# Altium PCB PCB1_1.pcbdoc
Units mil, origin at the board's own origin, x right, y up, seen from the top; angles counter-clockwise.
Board outline 1868.98 x 1415 mil, 2 copper layers (Top Layer, Bottom Layer); 8 components, 14 nets, 46 pads, 14 vias.
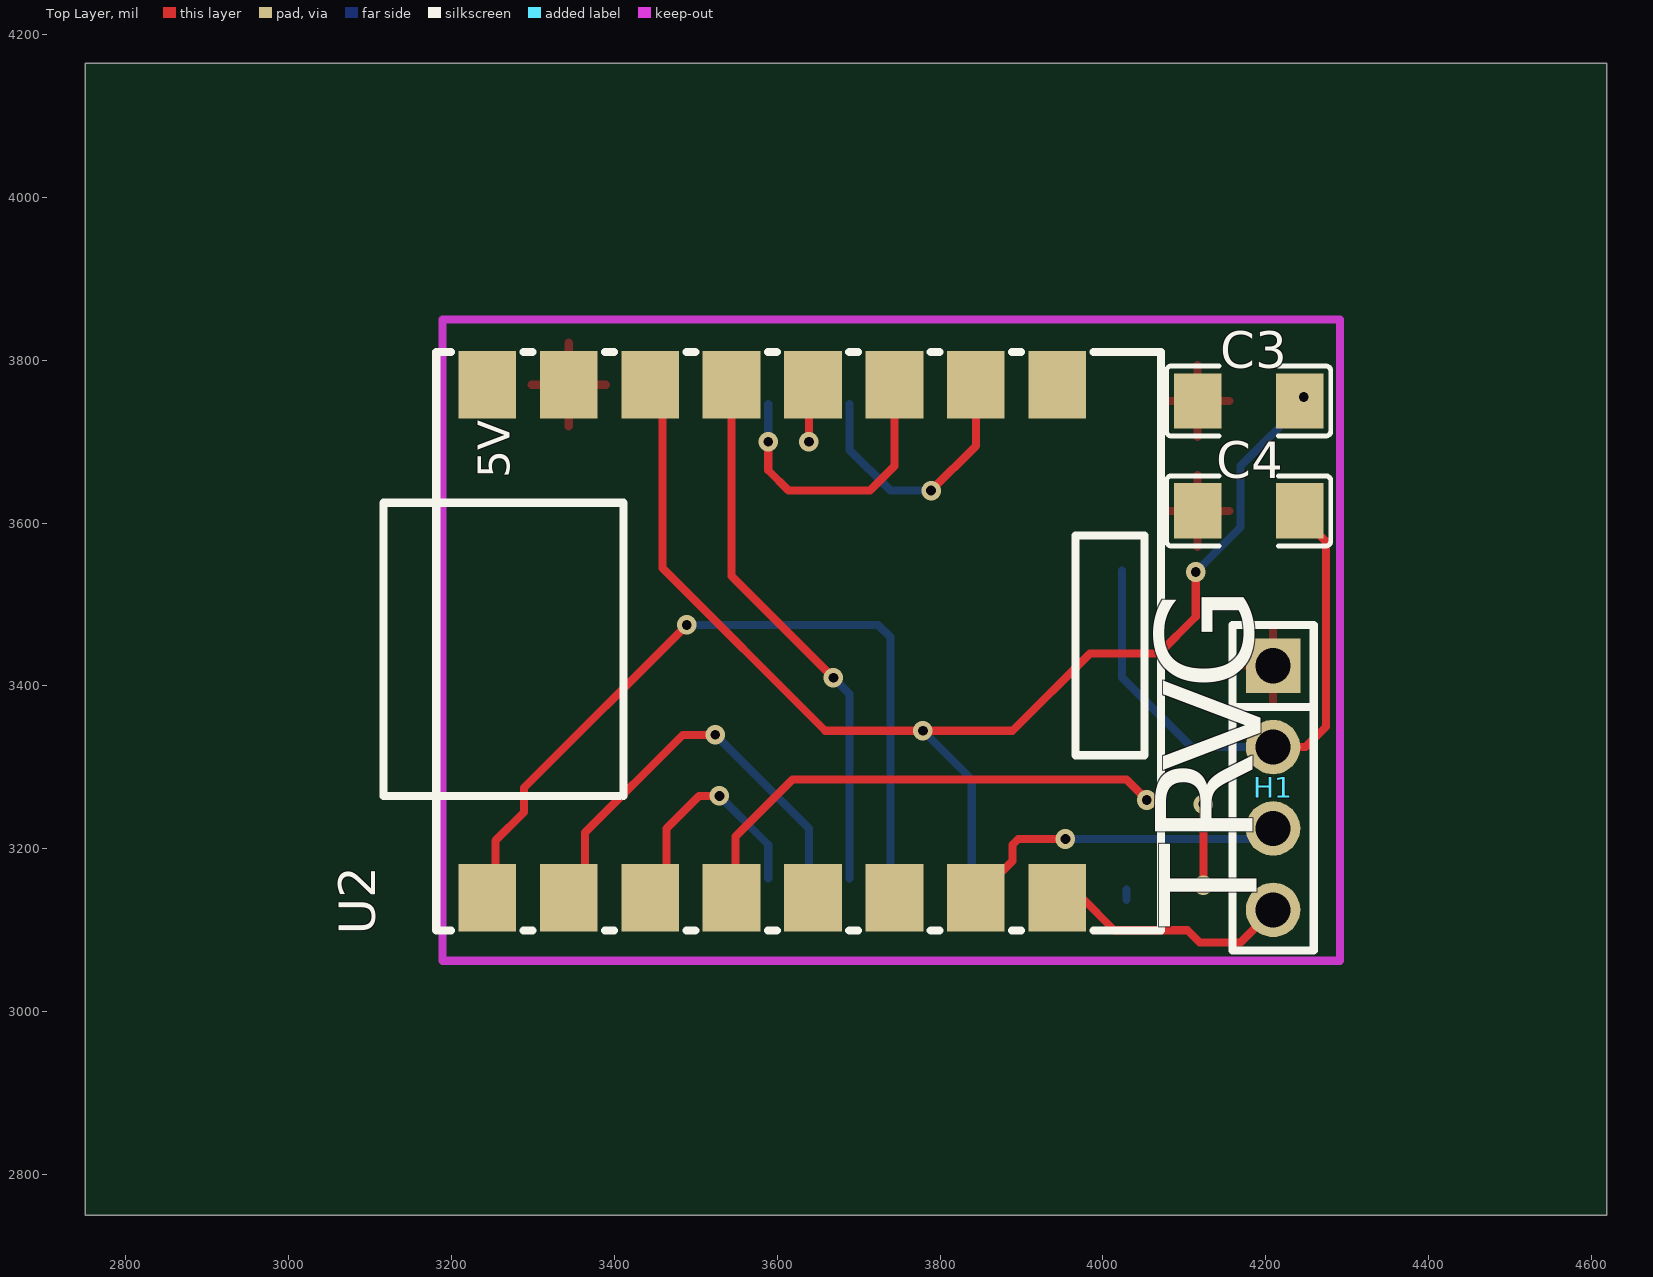
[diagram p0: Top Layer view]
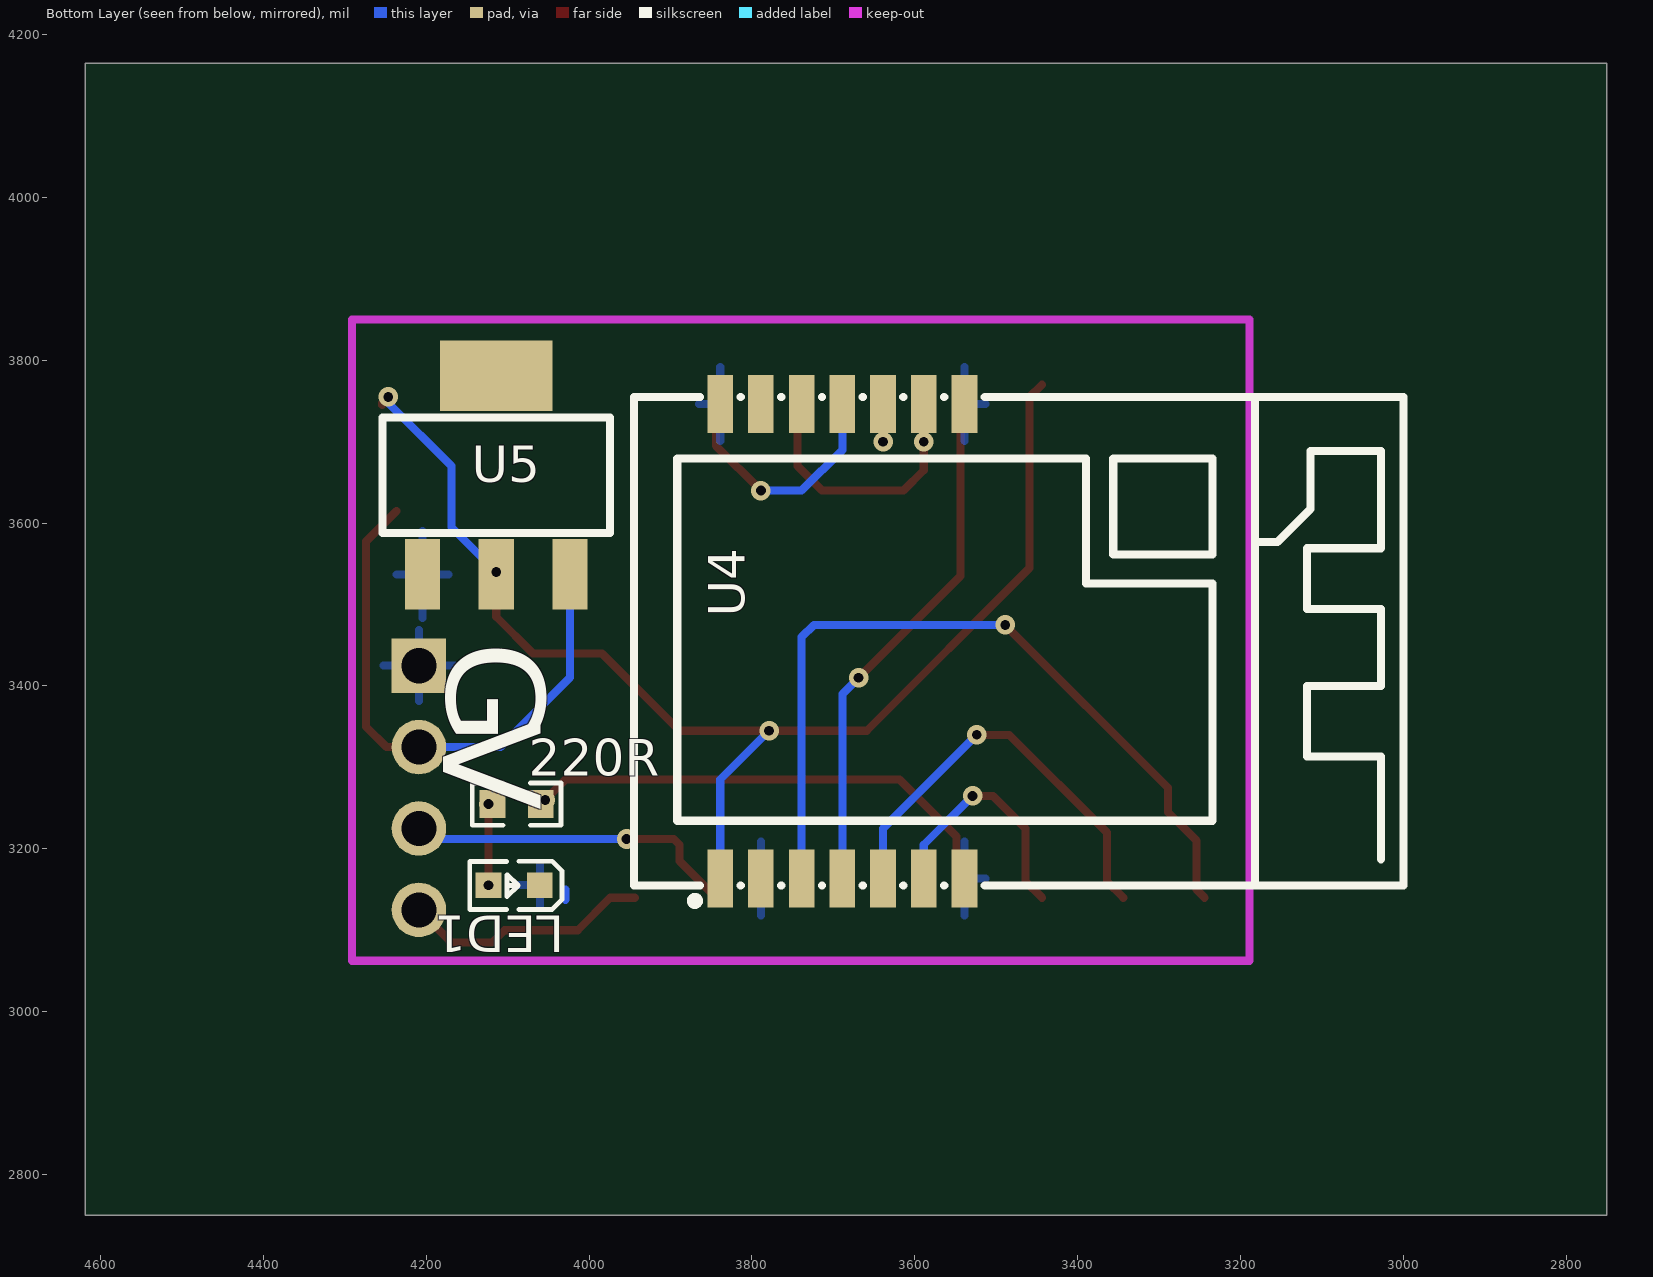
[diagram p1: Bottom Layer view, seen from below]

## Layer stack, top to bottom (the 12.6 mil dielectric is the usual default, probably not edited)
Top Layer: signal copper (thickness not stored)
Dielectric: dielectric 12.6, FR-4, Dk 4.8
Bottom Layer: signal copper (thickness not stored)

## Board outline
4618.98,2750 2750,2750 2750,4165 4618.98,4165

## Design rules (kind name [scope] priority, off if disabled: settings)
BoardOutlineClearance copperThickness1oz [All] p0: genericclearance=10 ignorepadtopadclearanceinfootprint=FALSE except(0: Arc-SplitContinuation Track-SplitContinuation SMDPad-SplitContinuation THPad-SplitContinuation Via-SplitContinuation Fill-SplitContinuation Poly-SplitContinuation Region-SplitContinuation Text-SplitContinuation; 6: Track-CutoutEdge SMDPad-CutoutEdge THPad-CutoutEdge Via-CutoutEdge Region-CutoutEdge; 11.8: Track-OutlineEdge SMDPad-OutlineEdge THPad-OutlineEdge Via-OutlineEdge Fill-OutlineEdge Region-OutlineEdge Poly-OutlineEdge Text-OutlineEdge Fill-CutoutEdge)
BoardOutlineClearance copperThickness2oz [All] p0: genericclearance=10 ignorepadtopadclearanceinfootprint=FALSE except(0: Arc-SplitContinuation Track-SplitContinuation SMDPad-SplitContinuation THPad-SplitContinuation Via-SplitContinuation Fill-SplitContinuation Poly-SplitContinuation Region-SplitContinuation Text-SplitContinuation; 6: Track-CutoutEdge SMDPad-CutoutEdge THPad-CutoutEdge Via-CutoutEdge Region-CutoutEdge; 11.8: Track-OutlineEdge SMDPad-OutlineEdge THPad-OutlineEdge Via-OutlineEdge Fill-OutlineEdge Region-OutlineEdge Poly-OutlineEdge Text-OutlineEdge Fill-CutoutEdge)
Clearance copperThickness1oz [(InNet('+3.3V') OR InNet('GND') OR InNet('VCC') OR InNet('$1N1206') OR InNet('$1N1200') OR InNet('$1N903') OR InNet('$1N951') OR InNet('$1N925') OR InNet('$1N893') OR InNet('$1N939') OR InNet('$1N882') OR InNet('$1N919') OR InNet('$1N1934') OR InNet('$1N1958'))] p1: gap=7 ignorepadtopadclearanceinfootprint=FALSE except(4: Track-Track; 6: Track-SMDPad SMDPad-SMDPad Track-THPad SMDPad-THPad THPad-THPad Track-Via SMDPad-Via THPad-Via Via-Via SMDPad-Fill THPad-Fill Via-Fill Fill-Fill Track-Region SMDPad-Region THPad-Region Via-Region Region-Region Track-Poly SMDPad-Poly THPad-Poly Via-Poly Fill-Poly Region-Poly Poly-Poly Track-Text SMDPad-Text THPad-Text Via-Text Fill-Text Region-Text Poly-Text Text-Text; 6.9: Track-Hole SMDPad-Hole THPad-Hole Via-Hole Fill-Hole Region-Hole Poly-Hole Text-Hole Sheet-Hole; 11.8: Track-Fill Fill-Region Track-Sheet SMDPad-Sheet THPad-Sheet Via-Sheet Fill-Sheet Region-Sheet Poly-Sheet Text-Sheet)
Clearance copperThickness2oz [All] p1: gap=7 ignorepadtopadclearanceinfootprint=FALSE except(6: Track-SMDPad SMDPad-SMDPad Track-THPad SMDPad-THPad THPad-THPad Track-Via SMDPad-Via THPad-Via Via-Via SMDPad-Fill THPad-Fill Via-Fill Fill-Fill Track-Region SMDPad-Region THPad-Region Via-Region Region-Region Track-Poly SMDPad-Poly THPad-Poly Via-Poly Fill-Poly Region-Poly Poly-Poly Track-Text SMDPad-Text THPad-Text Via-Text Fill-Text Region-Text Poly-Text Text-Text; 6.9: Track-Hole SMDPad-Hole THPad-Hole Via-Hole Fill-Hole Region-Hole Poly-Hole Text-Hole Sheet-Hole; 8: Track-Track; 11.8: Track-Fill Fill-Region Track-Sheet SMDPad-Sheet THPad-Sheet Via-Sheet Fill-Sheet Region-Sheet Poly-Sheet Text-Sheet)
DiffPairsRouting differentialPair [All] p1: maxuncoupledlength=10 minlimit=6 maxlimit=6 mostfreqgap=6 toplayer_minwidth=5 toplayer_prefwidth=10 toplayer_maxwidth=100 bottomlayer_minwidth=5 bottomlayer_prefwidth=10 bottomlayer_maxwidth=100
PasteMaskExpansion pasteMaskExpansion [All] p1: expansion=0
PlaneConnect innerPlane [All] p1: planeconnectstyle=Relief reliefexpansion=20 reliefentries=4 reliefconductorwidth=10 reliefairgap=10
PolygonConnect copperRegion [All] p1: connectstyle=Relief reliefentries=4 reliefconductorwidth=10 polygonreliefangle="90 Angle" airgapwidth=10
RoutingVias viaSize [All] p1: viastyle="Through Hole" holewidth=12.0078 minholewidth=11.811 maxholewidth=248.0314 width=24.0158 minwidth=19.685 maxwidth=393.7008
SolderMaskExpansion solderMaskExpansion [All] p1: useseparateexpansions=TRUE expansion=2 expansionbottom=2
Width copperThickness1oz [All] p1: maxlimit=100 minlimit=5 preferedwidth=10
Width copperThickness2oz [All] p1: maxlimit=100 minlimit=8 preferedwidth=10

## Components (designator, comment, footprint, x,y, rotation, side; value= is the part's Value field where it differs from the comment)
220R "Res_0603" R0603 4088.98,3255 r180 bottom
C3 "GRM31CR61A107MEA8L" C1206 4178.98,3750 r0 top
C4 "GRM31CR61A107MEA8L" C1206 4178.98,3615 r0 top
H1 "PZ254V-11-04P" HDR-TH_4P-P2.54-V-M 4208.98,3275 r270 top
LED1 "LED_0603-R" LED_0603 4093.98,3155 r0 bottom
U2 "ESP32C3-SuperMini" COMM-SMD_16P-L22.5-W18.0-P2.54-TL 3593.98,3455 r90 top
U4 "E28-2G4M12S" WIRELM-SMD_E28-2G4M12S 3688.98,3455 r90 bottom
U5 "AMS1117" SOT_223 4113.98,3660 r180 bottom

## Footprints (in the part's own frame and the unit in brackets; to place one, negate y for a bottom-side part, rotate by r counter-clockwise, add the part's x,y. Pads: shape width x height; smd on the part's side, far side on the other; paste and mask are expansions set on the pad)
C1206 [mm]
  rect 1.485x1.728 smd: 1(-1.593,0) 2(1.593,0)
  silkscreen extent -2.56,-1.09 2.56,1.09
COMM-SMD_16P-L22.5-W18.0-P2.54-TL [mil]
  rect 82.76x70.94 smd: 1(-315,350) 2(-315,250) 3(-315,150) 4(-315,50) 5(-315,-50) 6(-315,-150) 7(-315,-250) 8(-315,-350) 9(315,-350) 10(315,-250) 11(315,-150) 12(315,-50) 13(315,50) 14(315,150) 15(315,250) 16(315,350)
  silkscreen extent -355,-477 355,478
HDR-TH_4P-P2.54-V-M [mm]
  rect 1.7x1.7 hole 1.1: 1(-3.81,0)
  round 1.7 hole 1.1: 2(-1.27,0) 3(1.27,0) 4(3.81,0)
  silkscreen extent -5.08,-1.27 5.08,1.27
LED_0603 [mil]
  rect 31.5x31.5 smd: 1(-33.5,-0.4) 2(29.5,-0.2)
  silkscreen extent -61,-30 53,30
R0603 [mil]
  rect 31.75x34.02 smd: 1(-29.66,0) 2(29.66,0)
  silkscreen extent -55,-26 55,26
SOT_223 [mil]
  rect 43.3x86.6 smd: 1(-90.5,-123.05) 2(0,-123.05) 3(90.6,-123.05)
  rect 137.8x86.6 smd: 4(0,120.95)
  silkscreen extent -140,-72 140,70
WIRELM-SMD_E28-2G4M12S [mm]
  rect 1.8x0.8 smd: 1(-7.4,3.81) 2(-7.4,2.54) 3(-7.4,1.27) 4(-7.4,0) 5(-7.4,-1.27) 6(-7.4,-2.54) 7(-7.4,-3.81) 8(7.4,-3.81) 9(7.4,-2.54) 10(7.4,-1.27) 11(7.4,0) 12(7.4,1.27) 13(7.4,2.54) 14(7.4,3.81)
  silkscreen extent -8.22,-17.5 7.62,6.5

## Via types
v1: diameter 24.02, hole 12.01, Top Layer to Bottom Layer, 14 vias

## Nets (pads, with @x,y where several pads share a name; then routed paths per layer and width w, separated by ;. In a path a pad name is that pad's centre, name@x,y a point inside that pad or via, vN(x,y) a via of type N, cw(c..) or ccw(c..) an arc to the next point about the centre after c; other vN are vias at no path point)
$1N882: U2.12 U4.10 | length 118.4
  Top Layer w10: v1(3638.98,3700) 3638.98,3765 U2.12
  Bottom Layer w10: v1(3638.98,3700) U4.10
$1N893: U2.10 U4.11 | length 329.8
  Top Layer w10: v1(3788.98,3640) 3843.98,3695 U2.10
  Bottom Layer w10: U4.11 3688.98,3690 3738.98,3640 v1(3788.98,3640)
$1N903: U2.1 U4.3 | length 989
  Top Layer w10: U2.1 3253.98,3150 3253.98,3210 3288.98,3245 3288.98,3275 v1(3488.98,3475)
  Bottom Layer w10: v1(3488.98,3475) 3723.98,3475 3738.98,3460 U4.3
$1N919: U2.13 U4.4 | length 666.4
  Top Layer w10: U2.13 3543.98,3535 v1(3668.98,3410)
  Bottom Layer w10: v1(3668.98,3410) 3688.98,3390 U4.4
$1N925: U2.3 U4.6 | length 301
  Top Layer w10: U2.3 3463.98,3160 3463.98,3225 3503.98,3265 v1(3528.98,3265)
  Bottom Layer w10: v1(3528.98,3265) 3588.98,3205 U4.6
$1N939: U2.11 U4.9 | length 359.1
  Top Layer w10: v1(3588.98,3700) 3588.98,3665 3613.98,3640 3713.98,3640 3743.98,3670 U2.11
  Bottom Layer w10: v1(3588.98,3700) U4.9
$1N951: U2.2 U4.5 | length 522
  Top Layer w10: U2.2 3363.98,3160 3363.98,3220 3483.98,3340 v1(3523.98,3340)
  Bottom Layer w10: v1(3523.98,3340) 3638.98,3225 U4.5
$1N1200: 220R.2 U2.4 | length 628.8
  Top Layer w10: U2.4 3548.98,3145 3548.98,3215 3618.98,3285 4028.98,3285 v1(4053.98,3260)
  Bottom Layer w10: v1(4053.98,3260) 4058.98,3255 220R.2
$1N1206: 220R.1 LED1.2 | length 104.6
  Top Layer w10: v1(4123.48,3155.2) v1(4123.48,3255)
  Bottom Layer w10: 220R.1 v1(4123.48,3255)
$1N1934: H1.3 U2.7 | length 411.9
  Top Layer w10: U2.7 3888.98,3185 3888.98,3205 3896.05,3212.07 v1(3953.98,3212.07)
  Bottom Layer w10: v1(3953.98,3212.07) 4196.05,3212.07 H1.3
$1N1958: H1.4 U2.8 | length 304.4
  Top Layer w10: U2.8 3973.98,3140 4013.98,3100 4103.98,3100 4118.98,3085 4168.98,3085 H1.4
+3.3V: C3.2 U2.14 U4.1 U5.2 | length 1573.2
  Top Layer w10: U2.14 3458.98,3755 3458.98,3545 3658.98,3345 v1(3778.98,3345) 3888.98,3345 3983.98,3440 4068.98,3440 4113.98,3485 v1(4113.98,3540) ; v1(4246.68,3755) 4253.98,3747.7 C3.2@4253.98,3745
  Bottom Layer w10: v1(3778.98,3345) 3838.98,3285 U4.1 ; U5.2@4113.98,3541.95 v1(4113.98,3540) 4168.98,3595 4168.98,3670 4246.68,3747.7 v1(4246.68,3755)
GND: C3.1 C4.1 H1.1 LED1.1 U2.15 U4.2 U4.7 U4.8 U4.14 U5.1
VCC: C4.2 H1.2 U5.3 | length 708.2
  Top Layer w10: H1.2 4248.98,3325 4273.98,3350 4273.98,3577.7 C4.2@4236.68,3615
  Bottom Layer w10: U5.3@4023.38,3541.95 4023.38,3410.6 4108.98,3325 H1.2
pads on no net: U2.5 U2.6 U2.9 U2.16 U4.12 U4.13 U5.4
copper on no net: | length 12.5
  Bottom Layer w10: 4028.98,3137.52 4028.98,3150

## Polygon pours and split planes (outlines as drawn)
GND on Bottom Layer (solid, remove dead copper, pour order 4): 3018.98,3915 4368.98,3915 4368.98,3000 3018.98,3000
GND on Top Layer (solid, remove dead copper, pour order 2): 3068.98,3915 4328.98,3915 4328.98,3035 3068.98,3035

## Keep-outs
Board Outline Layer:
  lines w10: 3188.98,3062.6 4291.34,3062.6 4291.34,3850 3188.98,3850 3188.98,3062.6

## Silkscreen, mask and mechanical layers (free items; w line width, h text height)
Top Silkscreen Layer:
  text "G" at 4183.98,3395 h120 r90
  text "V" at 4193.98,3295 h120 r90
  text "R" at 4183.98,3205 h120 r90
  text "T" at 4188.98,3105 h120 r90
Bottom Silkscreen Layer:
  text "G" at 4173.98,3455 h120 r90
  text "V" at 4178.98,3360 h120 r90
